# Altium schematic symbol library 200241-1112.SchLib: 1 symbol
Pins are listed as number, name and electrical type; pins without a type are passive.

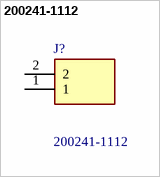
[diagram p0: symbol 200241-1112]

## 200241-1112
designator J?
MEGA-FIT V/T TOP LATCH ASSY TIN 2CKT BLK; Manufacturer_Name: Molex; Geometry.Height: 17.75mm
footprint 2002411112
pins: 1, 2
